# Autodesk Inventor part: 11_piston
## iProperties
Created: 2002-11
Part Number: 11_piston
Material: Par défaut
Document SubType Name: Modélisation
Designer: FIEVET
Control State: 0
Master: False
Checked Out: False
Shininess: 41.0
Length Units: 11269
Angle Units: 11279
Time Units: 11290
Mass Units: 11283
Length Display Precision: 3
Angle Display Precision: 2
Compacted: True
Density: 0.0
Volumn: 0.0
Area: 0.0
PropertySet Name: Model Information
Author: FIEVET
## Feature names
1. Révolution1 [Revolution]
2. Extrusion1
3. Extrusion2
